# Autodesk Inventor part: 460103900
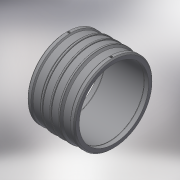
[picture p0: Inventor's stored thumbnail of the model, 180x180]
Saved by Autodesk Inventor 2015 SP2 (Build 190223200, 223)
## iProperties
Created: 2017-06
Part Number: 460103900
Material: Generic
Description: PLASSON LIGHTFIT COUPLER 900
Document SubType Name: Modeling
Designer: KIM
Mass: 72462.9 g
Surface Area: 34499.2 cm^2
Volume: 72462.9 cm^3
Density: 1 g/cm^3
Appearance: Default
Author: KIM
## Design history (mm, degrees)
derived "460103.ipt"
feature "Solid1::460103.ipt"
tag "TaggingFeature1"
body "Solid1"
other parameters: "d14" = 17.6296, "d19" = 3.52592, "d20" = 168 deg, "d23" = 1031, "d25" = 135 deg, "d27" = 135 deg, "d35" = 15, "d39" = 0, "d40" = 4, "d41" = 14, "d42" = 0, "d43" = 135 deg, "d44" = 55, "d48" = 1010.38, "d49" = 1031, "d50" = 5.155, "d51" = 6, "d52" = 0, "D_" = 1031, "d_2" = 12
